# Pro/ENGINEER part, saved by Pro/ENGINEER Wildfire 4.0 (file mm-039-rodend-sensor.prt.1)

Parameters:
  METRIC = "NO"

Other parameters: PITCH, DRILL_POINT_ANGLE, DRILL_DEPTH, DRILL_DIAMETER, THREAD_DIAMETER, THREADS_PER_INCH, THREAD_DEPTH, THREAD_LENGTH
